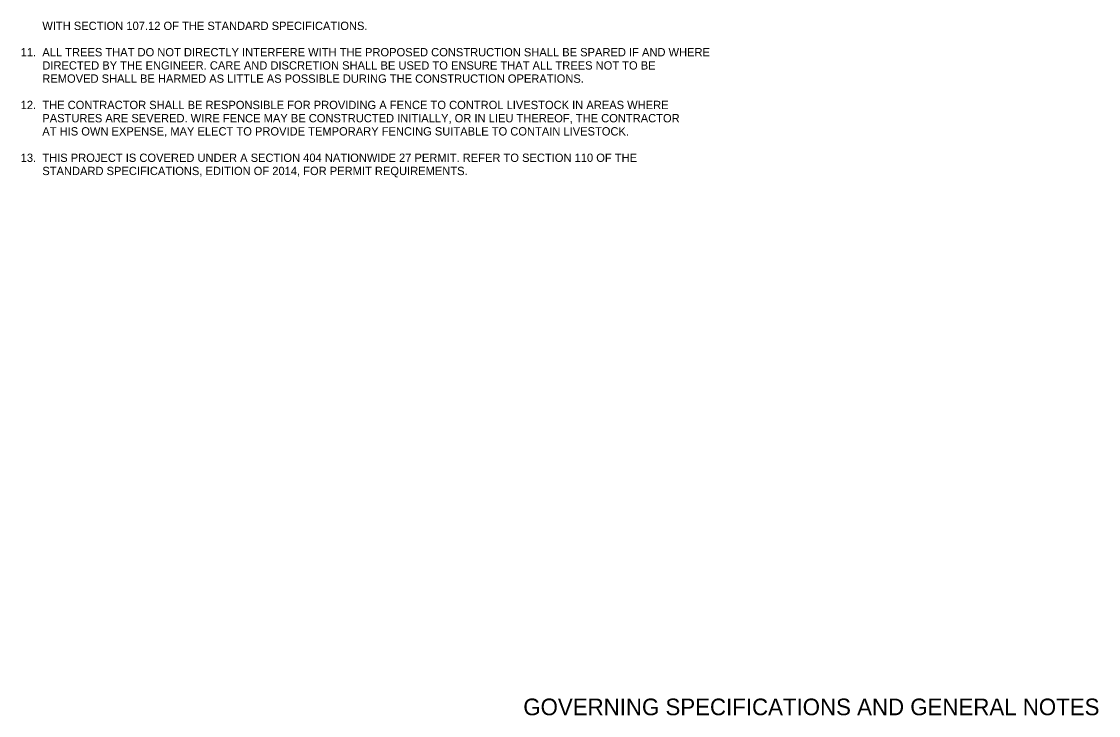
# Model space of a CAD drawing. Extents: x 1955708 to 1956002, y 566396 to 566594.
# Drawn here: x 1955839.4 to 1955994.7, y 566395.9 to 566496 of the extents above; entities that cross this region are included whole.
import ezdxf

# ---------------------------------------------------------------- set-up
doc = ezdxf.new("R2010")
doc.units = 0
doc.layers.add('Old_Level_1', color=7, linetype='Continuous')
doc.layers.add('R_Annotation', color=7, linetype='Continuous')

msp = doc.modelspace()

# ---------------------------------------------------------------- texts
at = {"layer": 'Old_Level_1'}
for s, p in [('       WITH SECTION 107.12 OF THE STANDARD SPECIFICATIONS.', (1955839.23, 566494.76)), ('11.  ALL TREES THAT DO NOT DIRECTLY INTERFERE WITH THE PROPOSED CONSTRUCTION SHALL BE SPARED IF AND WHERE', (1955839.23, 566490.96)), ('       DIRECTED BY THE ENGINEER. CARE AND DISCRETION SHALL BE USED TO ENSURE THAT ALL TREES NOT TO BE', (1955839.23, 566489.05)), ('       REMOVED SHALL BE HARMED AS LITTLE AS POSSIBLE DURING THE CONSTRUCTION OPERATIONS.', (1955839.23, 566487.15)), ('12.  THE CONTRACTOR SHALL BE RESPONSIBLE FOR PROVIDING A FENCE TO CONTROL LIVESTOCK IN AREAS WHERE', (1955839.23, 566483.35)), ('       PASTURES ARE SEVERED. WIRE FENCE MAY BE CONSTRUCTED INITIALLY, OR IN LIEU THEREOF, THE CONTRACTOR', (1955839.23, 566481.44)), ('       AT HIS OWN EXPENSE, MAY ELECT TO PROVIDE TEMPORARY FENCING SUITABLE TO CONTAIN LIVESTOCK.', (1955839.23, 566479.54)), ('13.  THIS PROJECT IS COVERED UNDER A SECTION 404 NATIONWIDE 27 PERMIT. REFER TO SECTION 110 OF THE', (1955839.23, 566475.73)), ('       STANDARD SPECIFICATIONS, EDITION OF 2014, FOR PERMIT REQUIREMENTS.', (1955839.23, 566473.83))]:
    msp.add_text(s, height=1.2, dxfattribs=at).set_placement(p)
at = {"layer": 'R_Annotation'}
msp.add_text('GOVERNING SPECIFICATIONS AND GENERAL NOTES', height=2.4, rotation=0, dxfattribs=at).set_placement((1955911.72, 566395.91))

doc.saveas('drawing.dxf')
